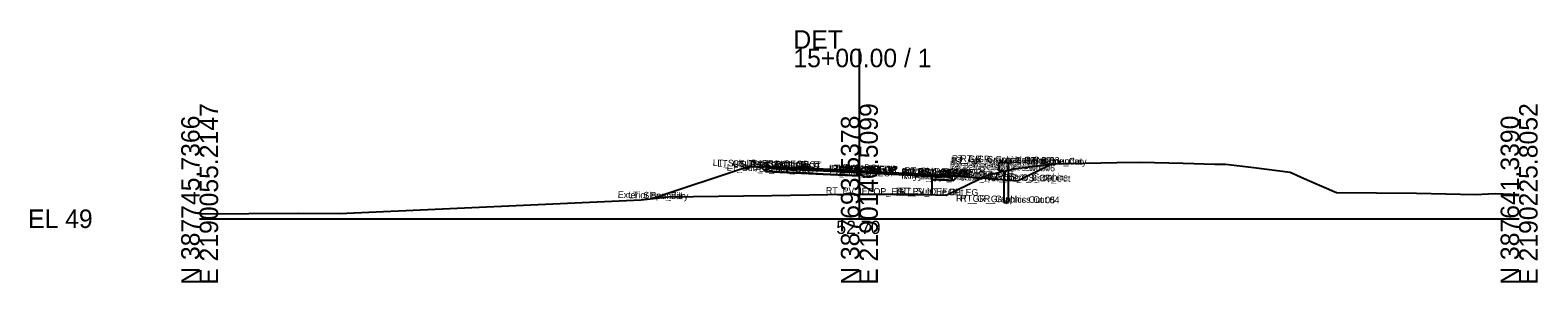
# Model space of a CAD drawing. Extents: x -26 to 1203, y -10 to 9543.
# Drawn here: x -25.7 to 202.8, y 4990.3 to 5028.5 of the extents above; entities that cross this region are included whole.
import ezdxf

# ---------------------------------------------------------------- set-up
doc = ezdxf.new("R2010")
doc.units = 0
for name, color, linetype in [('Default', 7, 'Continuous'), ('Exist CMT Pavement', 7, 'Continuous'), ('Exist Cross Section Cell', 7, 'Continuous'), ('Exist XS Center Line Elevation Label', 7, 'Continuous'), ('Exist XS Ground Line', 7, 'Continuous'), ('Prop CMT Guardrail Graphics', 7, 'Continuous'), ('Prop CMT Pvmt Course 1', 7, 'Continuous'), ('Prop CMT Pvmt Course 1 Wedge', 7, 'Continuous'), ('Prop CMT Pvmt Course 2', 7, 'Continuous'), ('Prop CMT Pvmt Course 2 Wedge', 7, 'Continuous'), ('Prop CMT Pvmt Course 3', 7, 'Continuous'), ('Prop CMT Pvmt Course 3 Wedge', 7, 'Continuous'), ('Prop CMT Pvmt Surface', 7, 'Continuous'), ('Prop CMT Pvmt Surface Shoulder', 7, 'Continuous'), ('Prop CMT Pvmt Wedge Surface 1', 7, 'Continuous'), ('Prop CMT Pvmt Wedge Surface 2', 7, 'Continuous'), ('Prop CMT Pvmt Wedge Surface 3', 7, 'Continuous'), ('Prop CMT Shld Paved Course 1', 7, 'Continuous'), ('Prop CMT Shld Paved Course 2', 7, 'Continuous'), ('Prop CMT Shld Paved Course 3', 7, 'Continuous'), ('Prop CMT Slope Grass', 7, 'Continuous'), ('Prop CMT Subgrade Earthwork', 7, 'Continuous'), ('Scratch_Level_0', 7, 'Continuous')]:
    doc.layers.add(name, color=color, linetype=linetype)

msp = doc.modelspace()

# ---------------------------------------------------------------- linework, layer by layer
at = {"layer": 'Exist CMT Pavement'}
msp.add_lwpolyline([(100, 5003.7), (111, 5003.61)], dxfattribs=at)
at = {"layer": 'Exist Cross Section Cell'}
for p, q in [((100, 5000), (100, 5025.73)), ((0, 5000), (100, 5000)), ((100, 5000), (200, 5000))]:
    msp.add_line(p, q, dxfattribs=at)
at = {"layer": 'Exist XS Ground Line'}
for p, q in [((119.43, 5006.59), (122.53, 5007.33)), ((122.53, 5007.33), (123.45, 5007.57)), ((123.45, 5007.57), (128.11, 5008.14)), ((128.11, 5008.14), (129.17, 5008.28)), ((129.17, 5008.28), (129.77, 5008.32)), ((129.77, 5008.32), (130.16, 5008.34)), ((130.16, 5008.34), (130.6, 5008.35)), ((130.6, 5008.35), (131.74, 5008.38)), ((131.74, 5008.38), (139.03, 5008.51)), ((139.03, 5008.51), (142.58, 5008.58)), ((142.58, 5008.58), (149.1, 5008.39)), ((149.1, 5008.39), (153.9, 5008.25)), ((153.9, 5008.25), (154.51, 5008.26)), ((154.51, 5008.26), (155.49, 5008.27)), ((155.49, 5008.27), (159.77, 5007.75)), ((159.77, 5007.75), (165.3, 5007.04)), ((113.17, 5003.55), (118.05, 5005.93)), ((118.05, 5005.93), (119.43, 5006.59)), ((165.3, 5007.04), (167.89, 5005.91)), ((167.89, 5005.91), (172.34, 5003.99)), ((22.3, 5000.84), (66.91, 5002.84)), ((66.91, 5002.84), (71.08, 5003.32)), ((71.08, 5003.32), (82.44, 5003.47)), ((82.44, 5003.47), (86.72, 5003.53)), ((86.72, 5003.53), (95.2, 5003.65)), ((95.2, 5003.65), (100, 5003.7)), ((100, 5003.7), (107.51, 5003.76)), ((107.51, 5003.76), (109.9, 5003.65)), ((109.9, 5003.65), (113.17, 5003.55)), ((172.34, 5003.99), (184.46, 5003.89)), ((184.46, 5003.89), (193.34, 5003.66)), ((193.34, 5003.66), (196.37, 5003.81)), ((196.37, 5003.81), (200, 5003.69)), ((0, 5000.72), (14.95, 5000.85)), ((14.95, 5000.85), (21.2, 5000.8)), ((21.2, 5000.8), (22.3, 5000.84))]:
    msp.add_line(p, q, dxfattribs=at)
at = {"layer": 'Prop CMT Guardrail Graphics'}
for points in [[(122.59, 5008.48), (121.25, 5008.48), (120.98, 5008.19)], [(120.98, 5008.19), (121.25, 5007.89)], [(121.25, 5007.89), (120.98, 5007.6)], [(120.98, 5007.6), (121.25, 5007.31), (121.92, 5007.31)], [(121.92, 5007.31), (121.92, 5002.48)], [(122.59, 5002.48), (122.59, 5008.48)], [(121.92, 5002.48), (122.59, 5002.48)]]:
    msp.add_lwpolyline(points, dxfattribs=at)
at = {"layer": 'Prop CMT Pvmt Course 1'}
for points in [[(100, 5007.24), (89, 5007.76)], [(89, 5007.76), (89, 5007.51)], [(89, 5007.51), (100, 5006.99)], [(100, 5006.99), (100, 5007.24)], [(100, 5007.24), (111, 5006.71)], [(100, 5006.99), (100, 5007.24)], [(111, 5006.59), (100, 5007.11)], [(100, 5007.11), (100, 5006.99), (100, 5006.99)], [(111, 5006.71), (111, 5006.46), (111, 5006.46), (111, 5006.59)]]:
    msp.add_lwpolyline(points, dxfattribs=at)
msp.add_lwpolyline([(100, 5006.99), (100, 5007.11), (100, 5007.11), (100, 5006.99)], close=True, dxfattribs=at)
at = {"layer": 'Prop CMT Pvmt Course 1 Wedge'}
msp.add_lwpolyline([(100, 5007.11), (111, 5006.59)], dxfattribs=at)
at = {"layer": 'Prop CMT Pvmt Course 2'}
for points in [[(89, 5007.51), (100, 5006.99)], [(100, 5006.99), (89, 5007.51)], [(89, 5007.51), (89, 5007.51)], [(100, 5006.99), (100, 5006.99)], [(111, 5006.46), (111, 5006.46)]]:
    msp.add_lwpolyline(points, dxfattribs=at)
msp.add_lwpolyline([(111, 5006.46), (111, 5006.46), (111, 5006.46)], close=True, dxfattribs=at)
at = {"layer": 'Prop CMT Pvmt Course 2 Wedge'}
msp.add_lwpolyline([(100, 5006.99), (111, 5006.46)], dxfattribs=at)
at = {"layer": 'Prop CMT Pvmt Course 3'}
for points in [[(100, 5006.99), (89, 5007.51)], [(89, 5007.51), (89, 5007.01)], [(89, 5007.01), (100, 5006.49)], [(100, 5006.49), (100, 5006.99)], [(111, 5006.46), (111, 5006.46), (111, 5005.96), (111, 5005.96)], [(111, 5005.96), (111, 5006.46)]]:
    msp.add_lwpolyline(points, dxfattribs=at)
at = {"layer": 'Prop CMT Pvmt Course 3 Wedge'}
msp.add_lwpolyline([(100, 5006.99), (111, 5006.46)], dxfattribs=at)
at = {"layer": 'Prop CMT Pvmt Surface'}
for points in [[(100, 5007.24), (89, 5007.76)], [(100, 5007.24), (111, 5006.71)]]:
    msp.add_lwpolyline(points, dxfattribs=at)
at = {"layer": 'Prop CMT Pvmt Surface Shoulder'}
for points in [[(89, 5007.76), (87, 5007.86)], [(111, 5006.71), (113, 5006.62)]]:
    msp.add_lwpolyline(points, dxfattribs=at)
at = {"layer": 'Prop CMT Pvmt Wedge Surface 1'}
for points in [[(100, 5007.11), (111, 5006.59)], [(111, 5006.46), (111, 5006.71)], [(111, 5006.59), (111, 5006.46), (111, 5006.46)]]:
    msp.add_lwpolyline(points, dxfattribs=at)
at = {"layer": 'Prop CMT Pvmt Wedge Surface 2'}
for points in [[(100, 5006.99), (111, 5006.46)], [(111, 5006.46), (111, 5006.71)]]:
    msp.add_lwpolyline(points, dxfattribs=at)
at = {"layer": 'Prop CMT Pvmt Wedge Surface 3'}
for points in [[(100, 5006.99), (111, 5006.46)], [(111, 5006.46), (111, 5006.71)]]:
    msp.add_lwpolyline(points, dxfattribs=at)
at = {"layer": 'Prop CMT Shld Paved Course 1'}
for points in [[(89, 5007.76), (87, 5007.86), (86.76, 5007.62)], [(86.76, 5007.62), (89, 5007.51)], [(89, 5007.51), (89, 5007.76)], [(111, 5006.71), (113, 5006.62), (113.26, 5006.35)], [(111, 5006.46), (111, 5006.71)], [(113.26, 5006.35), (111, 5006.46)]]:
    msp.add_lwpolyline(points, dxfattribs=at)
at = {"layer": 'Prop CMT Shld Paved Course 2'}
for points in [[(89, 5007.51), (86.76, 5007.62)], [(86.76, 5007.62), (86.76, 5007.62)], [(86.76, 5007.62), (89, 5007.51)], [(89, 5007.51), (89, 5007.51)], [(111, 5006.46), (113.26, 5006.35)], [(113.26, 5006.35), (111, 5006.46)], [(111, 5006.46), (111, 5006.46)], [(113.26, 5006.35), (113.26, 5006.35)]]:
    msp.add_lwpolyline(points, dxfattribs=at)
at = {"layer": 'Prop CMT Shld Paved Course 3'}
for points in [[(89, 5007.51), (86.76, 5007.62), (86.26, 5007.64), (85.78, 5007.16)], [(85.78, 5007.16), (89, 5007.01)], [(89, 5007.01), (89, 5007.51)], [(111, 5006.46), (113.26, 5006.35), (113.76, 5006.33), (114.29, 5005.8)], [(111, 5005.96), (111, 5006.46)], [(114.29, 5005.8), (111, 5005.96)]]:
    msp.add_lwpolyline(points, dxfattribs=at)
at = {"layer": 'Prop CMT Slope Grass'}
for points in [[(87, 5007.86), (83, 5007.81), (68.71, 5003.04)], [(123.98, 5005.74), (123.99, 5005.73), (129.06, 5008.27)], [(113, 5006.62), (120.98, 5005.98)], [(120.98, 5005.98), (123.98, 5005.74)]]:
    msp.add_lwpolyline(points, dxfattribs=at)
at = {"layer": 'Prop CMT Subgrade Earthwork'}
for points in [[(85.78, 5007.16), (85.12, 5007.83)], [(89, 5007.01), (85.78, 5007.16)], [(100, 5006.49), (89, 5007.01)], [(111, 5005.96), (111, 5005.96)], [(111, 5005.96), (111, 5003.61)], [(111, 5005.96), (114.29, 5005.8)], [(114.29, 5005.8), (114.94, 5006.46)]]:
    msp.add_lwpolyline(points, dxfattribs=at)

# ---------------------------------------------------------------- texts
at = {"layer": 'Default'}
msp.add_text('-', height=0.0001, dxfattribs=at).set_placement((0, 5000))
at = {"layer": 'Exist Cross Section Cell'}
for s, p in [('DET', (90, 5025.73)), ('15+00.00 / 1', (90, 5022.93)), ('EL 49', (-26, 4998.6))]:
    msp.add_text(s, height=2.8, dxfattribs=at).set_placement(p)
for s, p in [('E 2190055.2147', (2.8, 4990)), ('E 2190140.5099', (102.8, 4990)), ('E 2190225.8052', (202.8, 4990)), ('N 387745.7366', (0, 4990)), ('N 387693.5378', (100, 4990)), ('N 387641.3390', (200, 4990))]:
    msp.add_text(s, height=2.8, rotation=90, dxfattribs=at).set_placement(p)
at = {"layer": 'Exist XS Center Line Elevation Label'}
msp.add_text('52.70', height=2, dxfattribs=at).set_placement((96.5, 4997.7))
at = {"layer": 'Scratch_Level_0'}
for s, p in [('RT_GR_Graphics Out 02', (114, 5008.62)), ('RT_GR_Graphics Out 03', (115.31, 5008.62)), ('LT_Sub_Trench_Out_DLT', (77.77, 5007.98)), ('LT_GS_OS_CTL', (78.46, 5007.9)), ('LT_Sub_Trench_Out', (79.89, 5007.28)), ('LT_PS3_Shelf_Out', (80.92, 5007.75)), ('LT_PS3_OEOP', (82.55, 5007.7)), ('LT_PS2_OEOP', (82.55, 5007.7)), ('LT_PS1_OEOP', (82.91, 5007.94)), ('LT_PV2_OEOT', (84.75, 5007.59)), ('LT_PV3_OEOT', (84.75, 5007.59)), ('LT_Sub_OEOT', (84.77, 5007.09)), ('LT_PV1_OEOT', (84.87, 5007.84)), ('LT_PV2_OEEOP', (95.39, 5007.08)), ('LT_PV3_OEEOP', (95.39, 5007.08)), ('LT_Sub_OEEOP', (95.42, 5006.58)), ('LT_PV1_OEEOP', (95.51, 5007.2)), ('RT_PV2_IEEOP', (95.71, 5007.07)), ('RT_PV3_IEEOP', (95.71, 5007.07)), ('LT_PV2_IEEOP', (95.77, 5007.07)), ('RT_PV1_IEEOP', (95.83, 5007.19)), ('LT_PV1_IEEOP', (95.89, 5007.19)), ('PV2_PGL', (97.35, 5007.04)), ('PV1_PGL', (97.47, 5007.29)), ('RT_PV2_OEEOP', (106.33, 5006.55)), ('RT_PV3_OEEOP', (106.33, 5006.55)), ('RT_PV1_OEEOP', (106.45, 5006.67)), ('RT_PV3_OEOT', (106.69, 5006.55)), ('RT_PV2_OEOT', (106.69, 5006.55)), ('RT_PV1_OEOT', (106.81, 5006.79)), ('RT_Sub_Trench_Out_DLT', (107.54, 5006.6)), ('RT_PS3_Shelf_Out', (108.36, 5006.43)), ('RT_PS1_OEOP', (108.85, 5006.7)), ('RT_PS3_OEOP', (108.99, 5006.44)), ('RT_PS2_OEOP', (108.99, 5006.44)), ('RT_GS_OS_GR_Face_Graphics', (111.92, 5006.15)), ('RT_GR_Graphics Out 08', (113.7, 5007.74)), ('RT_GR_Graphics Out 01', (113.87, 5008.32)), ('RT_GR_Graphics Out 07', (113.95, 5007.45)), ('RT_GR_Graphics Out 09', (113.97, 5008.04)), ('RT_GR_Graphics Out 06', (114.63, 5007.45)), ('Exterior Boundary', (123.72, 5008.37)), ('RT_Slope_Cut', (125, 5008.35)), ('RT_Sub_OEEOP', (106.36, 5006.05)), ('RT_Sub_OEOT', (106.71, 5006.04)), ('RT_Sub_Trench_Out', (108.34, 5005.92)), ('RT_SS_Ditch_Base_Out', (117.19, 5005.87)), ('RT_GS_OS_CTL', (119.39, 5005.83)), ('Exterior Boundary', (63.37, 5003.15)), ('LT_Slope_Fill', (64.95, 5003.12)), ('RT_PV_IEEOP_EG', (94.92, 5003.8)), ('RT_PV_OEEOP_EG', (105.54, 5003.72)), ('RT_Sub Tie Out', (106.1, 5003.71)), ('RT_GR_Graphics Out 05', (114.64, 5002.62)), ('RT_GR_Graphics Out 04', (115.3, 5002.62))]:
    msp.add_text(s, height=1, rotation=358.8836, dxfattribs=at).set_placement(p)

doc.saveas('drawing.dxf')
